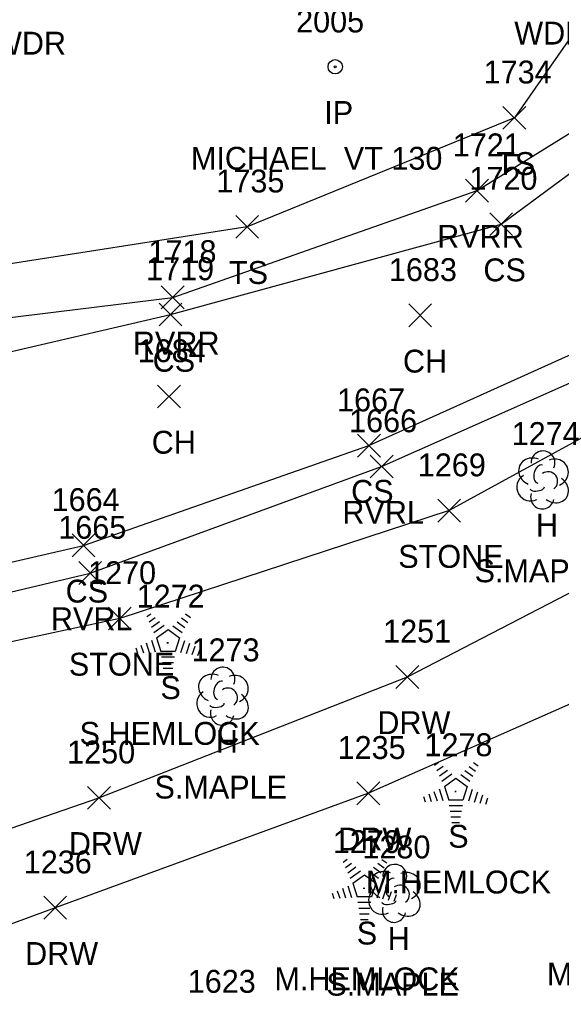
# Model space of a CAD drawing. Extents: x 1621633 to 1624015, y 417863 to 420979.
# Drawn here: x 1621891.2 to 1621938.6, y 417982.6 to 418067.9 of the extents above; entities that cross this region are included whole.
import ezdxf

# ---------------------------------------------------------------- set-up
doc = ezdxf.new("R2010")
doc.units = 0
for name, color, linetype in [('L_A', 7, 'Continuous'), ('L_C', 7, 'Continuous'), ('L_I', 7, 'Continuous'), ('L_TIC', 7, 'Continuous'), ('LASF', 7, 'Continuous'), ('LAWE', 7, 'Continuous'), ('LELB', 7, 'Continuous'), ('LTC', 7, 'Continuous'), ('LTD', 7, 'Continuous'), ('M_A', 7, 'Continuous'), ('M_C', 7, 'Continuous'), ('M_I', 7, 'Continuous'), ('MPIR', 7, 'Continuous'), ('R_A', 7, 'Continuous'), ('R_I', 7, 'Continuous'), ('R_TIC', 7, 'Continuous'), ('RDW', 7, 'Continuous')]:
    doc.layers.add(name, color=color, linetype=linetype)

msp = doc.modelspace()

# ---------------------------------------------------------------- linework, layer by layer
at = {"layer": 'L_TIC'}
for points in [[(1621933.526, 418058.292), (1621935.526, 418060.292)], [(1621935.526, 418058.292), (1621933.526, 418060.292)], [(1621930.259, 418051.925), (1621932.259, 418053.925)], [(1621932.259, 418051.925), (1621930.259, 418053.925)], [(1621932.372, 418048.997), (1621934.372, 418050.997)], [(1621934.372, 418048.997), (1621932.372, 418050.997)], [(1621910.153, 418048.766), (1621912.153, 418050.766)], [(1621912.153, 418048.766), (1621910.153, 418050.766)], [(1621903.646, 418042.594), (1621905.646, 418044.594)], [(1621905.646, 418042.594), (1621903.646, 418044.594)], [(1621903.446, 418041.094), (1621905.446, 418043.094)], [(1621905.446, 418041.094), (1621903.446, 418043.094)], [(1621925.289, 418041.02), (1621927.289, 418043.02)], [(1621927.289, 418041.02), (1621925.289, 418043.02)], [(1621903.317, 418033.927), (1621905.317, 418035.927)], [(1621905.317, 418033.927), (1621903.317, 418035.927)], [(1621920.805, 418029.632), (1621922.805, 418031.632)], [(1621922.805, 418029.632), (1621920.805, 418031.632)], [(1621921.912, 418027.804), (1621923.912, 418029.804)], [(1621923.912, 418027.804), (1621921.912, 418029.804)], [(1621927.826, 418023.949), (1621929.826, 418025.949)], [(1621929.826, 418023.949), (1621927.826, 418025.949)], [(1621895.837, 418020.913), (1621897.837, 418022.913)], [(1621897.837, 418020.913), (1621895.837, 418022.913)], [(1621896.422, 418018.495), (1621898.422, 418020.495)], [(1621898.422, 418018.495), (1621896.422, 418020.495)], [(1621899.016, 418014.523), (1621901.016, 418016.523)], [(1621901.016, 418014.523), (1621899.016, 418016.523)]]:
    msp.add_lwpolyline(points, dxfattribs=at)
at = {"layer": 'LASF'}
msp.add_lwpolyline([(1622002.675, 418093.219), (1621997.296, 418076.86), (1621980.179, 418056.204), (1621954.756, 418039.139), (1621928.826, 418024.949), (1621900.016, 418015.523), (1621882.357, 418011.741)], dxfattribs=at)
at = {"layer": 'LAWE'}
for points in [[(1621694.469, 417944.857), (1621713.846, 417956.733), (1621742.172, 417966.049), (1621760.532, 417975.456), (1621777.237, 417983.398), (1621792.696, 417991.301), (1621817.095, 418001.163), (1621844.467, 418008.037), (1621871.363, 418013.308), (1621897.422, 418019.495), (1621922.912, 418028.804), (1621945.859, 418038.978), (1621969.359, 418051.535), (1621990.012, 418069.674), (1621996.064, 418084.217), (1621996.533, 418092.287)], [(1621682.822, 417967.998), (1621698.064, 417979.126), (1621716.448, 417990.621), (1621740.687, 418004.296), (1621760.276, 418012.676), (1621779.786, 418018.1), (1621807.782, 418023.044), (1621832.841, 418028.899), (1621852.452, 418034.783), (1621876.37, 418040.125), (1621904.646, 418043.594), (1621931.259, 418052.925), (1621950.617, 418064.927), (1621964.804, 418074.349), (1621971.864, 418081.724)]]:
    msp.add_lwpolyline(points, dxfattribs=at)
at = {"layer": 'LELB'}
for points in [[(1621694.018, 417945.604), (1621713.058, 417958.392), (1621741.418, 417968.002), (1621759.92, 417977.729), (1621776.332, 417984.988), (1621792.046, 417992.579), (1621816.284, 418002.68), (1621844.088, 418009.589), (1621869.849, 418015.692), (1621896.837, 418021.913), (1621921.805, 418030.632), (1621944.897, 418041.057), (1621968.773, 418053.066), (1621989.111, 418070.538), (1621994.262, 418084.512), (1621994.522, 418092.07)], [(1621714.218, 417979.319), (1621742.211, 418002.577), (1621762.579, 418009.214), (1621780.28, 418013.608), (1621808.258, 418019.376), (1621833.473, 418026.83), (1621853.516, 418030.646), (1621878.098, 418035.973), (1621904.446, 418042.094), (1621933.372, 418049.997), (1621951.553, 418063.416), (1621967.003, 418072.955), (1621972.682, 418081.713), (1621977.304, 418089.793)], [(1621962.893, 418084.645), (1621941.499, 418069.284), (1621934.526, 418059.292), (1621911.153, 418049.766), (1621884.836, 418045.66), (1621868.891, 418041.418), (1621850.259, 418038.198), (1621830.712, 418031.899), (1621803.346, 418026.98), (1621784.312, 418024.309)]]:
    msp.add_lwpolyline(points, dxfattribs=at)
at = {"layer": 'LTC'}
for p, q in [((1621902.375, 418015.684), (1621902.73, 418015.941)), ((1621905.774, 418015.924), (1621906.193, 418015.619)), ((1621902.585, 418015.218), (1621903.114, 418015.602)), ((1621902.794, 418014.752), (1621903.498, 418015.264)), ((1621905.031, 418015.227), (1621905.711, 418014.734)), ((1621905.402, 418015.576), (1621905.952, 418015.176)), ((1621903.004, 418014.286), (1621903.882, 418014.924)), ((1621903.229, 418013.831), (1621904.24, 418014.566)), ((1621904.24, 418014.566), (1621905.237, 418013.841)), ((1621904.66, 418014.879), (1621905.47, 418014.29)), ((1621902.319, 418013.396), (1621902.59, 418012.561)), ((1621902.774, 418013.612), (1621903.105, 418012.593)), ((1621903.229, 418013.831), (1621903.616, 418012.638)), ((1621905.237, 418013.841), (1621904.846, 418012.638)), ((1621905.675, 418013.57), (1621905.337, 418012.531)), ((1621901.408, 418012.963), (1621901.56, 418012.495)), ((1621901.863, 418013.179), (1621902.075, 418012.528)), ((1621904.846, 418012.638), (1621903.616, 418012.638)), ((1621906.119, 418013.32), (1621905.832, 418012.435)), ((1621906.564, 418013.07), (1621906.327, 418012.34)), ((1621907.008, 418012.819), (1621906.821, 418012.245)), ((1621904.808, 418012.138), (1621903.663, 418012.138)), ((1621904.724, 418011.638), (1621903.736, 418011.638)), ((1621904.64, 418011.138), (1621903.809, 418011.138)), ((1621904.556, 418010.638), (1621903.881, 418010.638)), ((1621927.547, 418002.689), (1621927.901, 418002.947)), ((1621927.756, 418002.224), (1621928.286, 418002.608)), ((1621927.966, 418001.758), (1621928.67, 418002.269)), ((1621930.574, 418002.582), (1621931.124, 418002.182)), ((1621930.945, 418002.93), (1621931.364, 418002.625)), ((1621928.176, 418001.292), (1621929.054, 418001.93)), ((1621928.4, 418000.837), (1621929.412, 418001.572)), ((1621929.412, 418001.572), (1621930.409, 418000.847)), ((1621929.832, 418001.885), (1621930.641, 418001.296)), ((1621930.203, 418002.233), (1621930.882, 418001.739)), ((1621927.946, 418000.618), (1621928.276, 417999.599)), ((1621928.4, 418000.837), (1621928.787, 417999.644)), ((1621930.409, 418000.847), (1621930.018, 417999.644)), ((1621930.846, 418000.576), (1621930.509, 417999.537)), ((1621926.579, 417999.969), (1621926.731, 417999.501)), ((1621927.035, 418000.185), (1621927.246, 417999.534)), ((1621927.49, 418000.402), (1621927.761, 417999.567)), ((1621931.291, 418000.326), (1621931.004, 417999.441)), ((1621931.736, 418000.076), (1621931.499, 417999.346)), ((1621932.18, 417999.825), (1621931.993, 417999.251)), ((1621930.018, 417999.644), (1621928.787, 417999.644)), ((1621929.979, 417999.144), (1621928.835, 417999.144)), ((1621929.896, 417998.644), (1621928.907, 417998.644)), ((1621929.812, 417998.144), (1621928.98, 417998.144)), ((1621929.728, 417997.644), (1621929.053, 417997.644)), ((1621919.546, 417994.223), (1621919.901, 417994.481)), ((1621919.756, 417993.758), (1621920.285, 417994.142)), ((1621919.965, 417993.292), (1621920.669, 417993.803)), ((1621922.203, 417993.767), (1621922.882, 417993.273)), ((1621922.573, 417994.116), (1621923.123, 417993.716)), ((1621922.945, 417994.464), (1621923.364, 417994.159)), ((1621920.175, 417992.826), (1621921.053, 417993.464)), ((1621920.4, 417992.371), (1621921.411, 417993.106)), ((1621921.411, 417993.106), (1621922.408, 417992.381)), ((1621921.831, 417993.419), (1621922.641, 417992.83)), ((1621919.945, 417992.152), (1621920.276, 417991.133)), ((1621920.4, 417992.371), (1621920.787, 417991.178)), ((1621922.408, 417992.381), (1621922.017, 417991.178)), ((1621922.846, 417992.11), (1621922.508, 417991.071)), ((1621918.579, 417991.503), (1621918.731, 417991.035)), ((1621919.034, 417991.719), (1621919.246, 417991.068)), ((1621919.49, 417991.936), (1621919.761, 417991.101)), ((1621923.29, 417991.86), (1621923.003, 417990.975)), ((1621923.735, 417991.61), (1621923.498, 417990.88)), ((1621924.179, 417991.359), (1621923.993, 417990.785)), ((1621922.017, 417991.178), (1621920.787, 417991.178)), ((1621921.979, 417990.678), (1621920.834, 417990.678)), ((1621921.895, 417990.178), (1621920.907, 417990.178)), ((1621921.811, 417989.678), (1621920.98, 417989.678)), ((1621921.728, 417989.178), (1621921.053, 417989.178))]:
    msp.add_line(p, q, dxfattribs=at)
at = {"layer": 'LTD'}
for p, q in [((1621936.98, 418027.686), (1621936.98, 418027.686)), ((1621936.98, 418027.686), (1621936.98, 418027.686)), ((1621908.984, 418008.778), (1621908.984, 418008.778)), ((1621908.984, 418008.778), (1621908.984, 418008.778)), ((1621924.016, 417991.546), (1621924.016, 417991.546)), ((1621924.016, 417991.546), (1621924.016, 417991.546))]:
    msp.add_line(p, q, dxfattribs=at)
for centre in [(1621937.027, 418029.12), (1621909.031, 418010.212), (1621924.063, 417992.98)]:
    msp.add_arc(centre, 1.047, 335.52715, 180.95627, dxfattribs=at)
for centre, major_axis, ratio, start_param, end_param in [((1621936.188, 418028.352), (1.21, -0.512), 0.895232, 1.570796, 4.712389), ((1621938.022, 418028.269), (-1.141, -0.483), 0.949671, 1.570796, 4.712389), ((1621936.772, 418028.144), (-0.208, -0.792), 0.645439, 3.141593, 6.283185), ((1621935.897, 418026.977), (0.584, -1.042), 0.959034, 3.141593, 6.283185), ((1621937.48, 418027.519), (-0.5, 0.667), 0.989748, 3.141593, 6.283185), ((1621936.522, 418026.936), (-0.625, -0.083), 0.423636, 0, 3.141593), ((1621937.98, 418026.852), (-1.09, 0.792), 0.841452, 1.570796, 4.712389), ((1621936.98, 418026.186), (0.265, 1.061), 0.942809, 1.570796, 4.712389), ((1621908.193, 418009.444), (1.21, -0.512), 0.895232, 1.570796, 4.712389), ((1621908.776, 418009.236), (-0.208, -0.792), 0.645439, 3.141593, 6.283185), ((1621910.026, 418009.361), (-1.141, -0.483), 0.949671, 1.570796, 4.712389), ((1621907.901, 418008.069), (0.584, -1.042), 0.959034, 3.141593, 6.283185), ((1621909.484, 418008.611), (-0.5, 0.667), 0.989748, 3.141593, 6.283185), ((1621909.985, 418007.944), (-1.09, 0.792), 0.841452, 1.570796, 4.712389), ((1621908.985, 418007.278), (0.265, 1.061), 0.942809, 1.570796, 4.712389), ((1621908.526, 418008.028), (-0.625, -0.083), 0.423636, 0, 3.141593), ((1621923.224, 417992.213), (1.21, -0.512), 0.895232, 1.570796, 4.712389), ((1621925.057, 417992.13), (-1.141, -0.483), 0.949671, 1.570796, 4.712389), ((1621923.807, 417992.004), (-0.208, -0.792), 0.645439, 3.141593, 6.283185), ((1621924.516, 417991.38), (-0.5, 0.667), 0.989748, 3.141593, 6.283185), ((1621922.933, 417990.838), (0.584, -1.042), 0.959034, 3.141593, 6.283185), ((1621925.016, 417990.713), (-1.09, 0.792), 0.841452, 1.570796, 4.712389), ((1621923.558, 417990.796), (-0.625, -0.083), 0.423636, 0, 3.141593), ((1621924.016, 417990.046), (0.265, 1.061), 0.942809, 1.570796, 4.712389)]:
    msp.add_ellipse(centre, major_axis=major_axis, ratio=ratio, start_param=start_param, end_param=end_param, dxfattribs=at)
at = {"layer": 'MPIR'}
for radius in [0.625, 0.0833]:
    msp.add_circle((1621918.853, 418063.754), radius, dxfattribs=at)
at = {"layer": 'R_TIC'}
for points in [[(1621924.17, 418009.412), (1621926.17, 418011.412)], [(1621926.17, 418009.412), (1621924.17, 418011.412)], [(1621897.189, 417998.842), (1621899.189, 418000.842)], [(1621899.189, 417998.842), (1621897.189, 418000.842)], [(1621920.756, 417999.239), (1621922.756, 418001.239)], [(1621922.756, 417999.239), (1621920.756, 418001.239)], [(1621893.363, 417989.232), (1621895.363, 417991.232)], [(1621895.363, 417989.232), (1621893.363, 417991.232)]]:
    msp.add_lwpolyline(points, dxfattribs=at)
at = {"layer": 'RDW'}
for points in [[(1622068.286, 418109.151), (1622048.314, 418092.064), (1622031.513, 418075.622), (1622017.283, 418070.416), (1621999.079, 418052.056), (1621978.461, 418032.933), (1621951.05, 418013.179), (1621921.756, 418000.239), (1621894.363, 417990.232), (1621865.95, 417979.751)], [(1621869.66, 417990.005), (1621898.189, 417999.842), (1621925.17, 418010.412), (1621952.262, 418024.445), (1621976.225, 418041.199), (1621996.59, 418062.054), (1622014.164, 418083.988), (1622019.779, 418092.569), (1622014.506, 418097.249)]]:
    msp.add_lwpolyline(points, dxfattribs=at)

# ---------------------------------------------------------------- texts
at = {"layer": 'L_A'}
for s, p in [('WDR', (1621934.515, 418065.696)), ('WDR', (1621888.924, 418064.816)), ('TS', (1621932.935, 418054.292)), ('RVRR', (1621927.77, 418047.925)), ('TS', (1621909.562, 418044.766)), ('CS', (1621931.813, 418044.997)), ('RVRR', (1621901.158, 418038.594)), ('CS', (1621902.887, 418037.094)), ('CH', (1621924.778, 418037.02)), ('CH', (1621902.805, 418029.927)), ('CS', (1621920.246, 418025.632)), ('RVRL', (1621919.479, 418023.804)), ('H', (1621936.413, 418022.686)), ('STONE', (1621924.369, 418019.949)), ('CS', (1621895.278, 418016.913)), ('RVRL', (1621893.989, 418014.495)), ('STONE', (1621895.559, 418010.523)), ('S', (1621903.566, 418008.475)), ('H', (1621908.417, 418003.778)), ('S', (1621928.738, 417995.481)), ('S', (1621920.737, 417987.015)), ('H', (1621923.449, 417986.546))]:
    msp.add_text(s, height=2, dxfattribs=at).set_placement(p)
at = {"layer": 'L_C'}
for s, p in [('S.MAPLE', (1621931.043, 418018.686)), ('S.HEMLOCK', (1621896.495, 418004.475)), ('S.MAPLE', (1621903.047, 417999.778)), ('M.HEMLOCK', (1621921.541, 417991.481)), ('M.ASH', (1621937.374, 417983.436)), ('M.HEMLOCK', (1621913.54, 417983.015)), ('S.MAPLE', (1621918.079, 417982.546))]:
    msp.add_text(s, height=2, dxfattribs=at).set_placement(p)
at = {"layer": 'L_I'}
for s, p in [('1734', (1621931.833, 418062.292)), ('1721', (1621929.133, 418055.925)), ('1735', (1621908.46, 418052.766)), ('1720', (1621930.592, 418052.997)), ('1718', (1621902.52, 418046.594)), ('1719', (1621902.312, 418045.094)), ('1683', (1621923.549, 418045.02)), ('1684', (1621901.577, 418037.927)), ('1667', (1621919.017, 418033.632)), ('1666', (1621920.069, 418031.804)), ('1274', (1621934.287, 418030.686)), ('1269', (1621926.078, 418027.949)), ('1664', (1621894.049, 418024.913)), ('1665', (1621894.635, 418022.495)), ('1270', (1621897.237, 418018.523)), ('1272', (1621901.487, 418016.475)), ('1273', (1621906.291, 418011.778)), ('1278', (1621926.659, 418003.481)), ('1279', (1621918.65, 417995.015)), ('1280', (1621921.236, 417994.546)), ('1623', (1621905.955, 417982.799))]:
    msp.add_text(s, height=2, dxfattribs=at).set_placement(p)
at = {"layer": 'LTC'}
for p in [(1621904.123, 418013.579), (1621929.294, 418000.585), (1621921.294, 417992.119)]:
    msp.add_text('.', height=1.037, rotation=270, dxfattribs=at).set_placement(p)
at = {"layer": 'M_A'}
msp.add_text('IP', height=2, dxfattribs=at).set_placement((1621917.9, 418058.754))
at = {"layer": 'M_C'}
msp.add_text('MICHAEL  VT 130', height=2, dxfattribs=at).set_placement((1621906.231, 418054.754))
at = {"layer": 'M_I'}
msp.add_text('2005', height=2, dxfattribs=at).set_placement((1621915.435, 418066.754))
at = {"layer": 'R_A'}
for p in [(1621922.54, 418005.412), (1621919.126, 417995.239), (1621895.559, 417994.842), (1621891.733, 417985.232)]:
    msp.add_text('DRW', height=2, dxfattribs=at).set_placement(p)
at = {"layer": 'R_I'}
for s, p in [('1251', (1621923.044, 418013.412)), ('1250', (1621895.409, 418002.842)), ('1235', (1621919.063, 418003.239)), ('1236', (1621891.615, 417993.232))]:
    msp.add_text(s, height=2, dxfattribs=at).set_placement(p)

doc.saveas('drawing.dxf')
